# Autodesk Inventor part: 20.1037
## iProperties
Created: 2013-02
Part Number: 20.1037
Material: PVC-U
Description: COVER 45X45 R
Document SubType Name: Modeling
Designer: Administrator
Density: 1.4 g/cm^3
Mass: 81.3527 g
Surface Area: 902.547 cm^2
Volume: 58.1091 cm^3
Author: Administrator
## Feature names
1. Extrusion1
